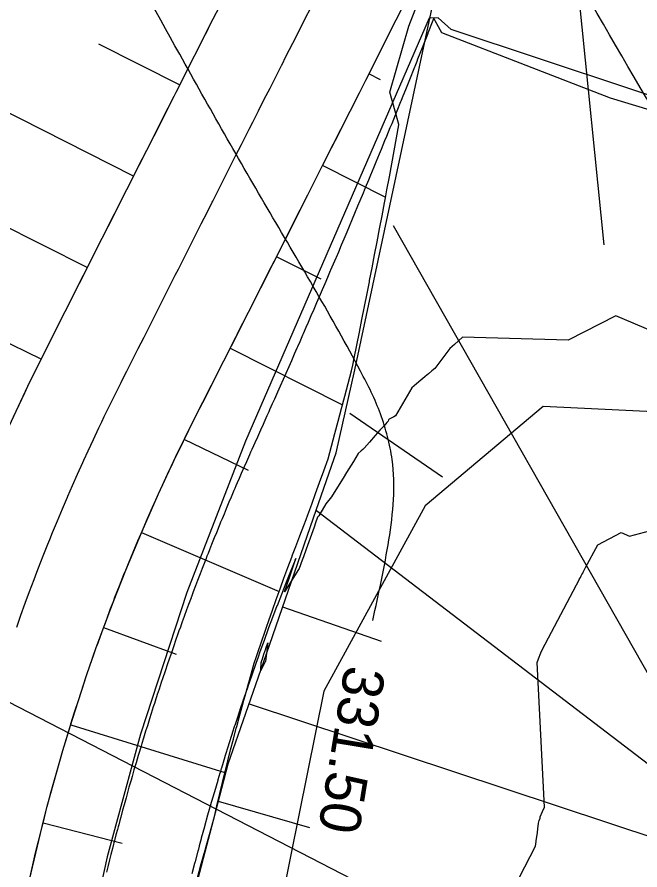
# Model space of a CAD drawing. Extents: x -564043 to -563833, y -1163561 to -1163412.
# Drawn here: x -563863.75 to -563856.15, y -1163500.35 to -1163489.94 of the extents above; entities that cross this region are included whole.
import ezdxf

# ---------------------------------------------------------------- set-up
doc = ezdxf.new("R2010")
doc.units = 0
for name, color, linetype in [('5', 7, 'Continuous'), ('Default', 7, 'Continuous'), ('Line', 7, 'Continuous'), ('Vrstva 24', 7, 'Continuous'), ('Vrstva 25', 7, 'Continuous'), ('Vrstva 26', 7, 'Continuous')]:
    doc.layers.add(name, color=color, linetype=linetype)

msp = doc.modelspace()

# ---------------------------------------------------------------- linework, layer by layer
for points in [[(-563863.593, -1163500.434), (-563863.56, -1163500.289), (-563863.526, -1163500.144), (-563863.491, -1163500), (-563863.455, -1163499.856), (-563863.446, -1163499.819), (-563863.419, -1163499.711), (-563863.383, -1163499.573), (-563863.381, -1163499.568), (-563863.343, -1163499.424), (-563863.304, -1163499.281), (-563863.264, -1163499.137), (-563863.223, -1163498.995), (-563863.193, -1163498.893), (-563863.181, -1163498.852), (-563863.138, -1163498.71), (-563863.104, -1163498.599), (-563863.094, -1163498.567), (-563863.05, -1163498.426), (-563863.004, -1163498.284), (-563862.958, -1163498.143), (-563862.911, -1163498.002), (-563862.903, -1163497.978), (-563862.863, -1163497.861), (-563862.814, -1163497.721), (-563862.785, -1163497.638), (-563862.764, -1163497.581), (-563862.714, -1163497.441), (-563862.662, -1163497.301), (-563862.61, -1163497.162), (-563862.576, -1163497.075), (-563862.557, -1163497.023), (-563862.503, -1163496.885), (-563862.448, -1163496.747), (-563862.426, -1163496.692), (-563862.392, -1163496.609), (-563862.335, -1163496.472), (-563862.278, -1163496.334), (-563862.219, -1163496.198), (-563862.214, -1163496.186), (-563862.16, -1163496.061), (-563862.1, -1163495.925), (-563862.039, -1163495.79), (-563862.026, -1163495.761), (-563861.978, -1163495.654), (-563861.915, -1163495.52), (-563861.852, -1163495.385), (-563861.817, -1163495.312), (-563861.787, -1163495.251), (-563861.722, -1163495.117), (-563861.657, -1163494.984), (-563861.59, -1163494.851), (-563861.589, -1163494.849), (-563861.52, -1163494.713), (-563861.45, -1163494.575), (-563861.38, -1163494.436), (-563861.31, -1163494.299), (-563861.24, -1163494.16), (-563861.17, -1163494.022), (-563861.1, -1163493.884), (-563861.031, -1163493.746), (-563860.961, -1163493.608), (-563860.928, -1163493.544), (-563860.891, -1163493.47), (-563860.821, -1163493.331), (-563860.751, -1163493.193), (-563860.681, -1163493.055), (-563860.611, -1163492.917), (-563860.541, -1163492.779), (-563860.477, -1163492.652), (-563860.471, -1163492.64), (-563860.401, -1163492.502), (-563860.331, -1163492.364), (-563860.261, -1163492.226), (-563860.192, -1163492.088), (-563860.122, -1163491.95), (-563860.052, -1163491.811), (-563860.026, -1163491.76), (-563859.982, -1163491.673), (-563859.912, -1163491.535), (-563859.842, -1163491.397), (-563859.772, -1163491.259), (-563859.702, -1163491.121), (-563859.632, -1163490.982), (-563859.63, -1163490.978), (-563859.574, -1163490.867), (-563859.495, -1163490.71), (-563859.123, -1163489.975), (-563858.671, -1163489.083)], [(-563861.556, -1163500.472), (-563861.521, -1163500.34), (-563861.512, -1163500.306), (-563861.485, -1163500.208), (-563861.45, -1163500.081), (-563861.449, -1163500.077), (-563861.412, -1163499.946), (-563861.374, -1163499.815), (-563861.34, -1163499.683), (-563861.309, -1163499.55), (-563861.286, -1163499.455), (-563861.277, -1163499.417), (-563861.245, -1163499.285), (-563861.219, -1163499.182), (-563861.212, -1163499.152), (-563861.179, -1163499.019), (-563861.145, -1163498.887), (-563861.111, -1163498.754), (-563861.076, -1163498.622), (-563861.07, -1163498.599), (-563861.041, -1163498.489), (-563861.005, -1163498.357), (-563860.984, -1163498.279), (-563860.969, -1163498.225), (-563860.932, -1163498.092), (-563860.895, -1163497.96), (-563860.857, -1163497.828), (-563860.83, -1163497.746), (-563860.814, -1163497.698), (-563860.769, -1163497.568), (-563860.725, -1163497.438), (-563860.707, -1163497.386), (-563860.68, -1163497.308), (-563860.634, -1163497.179), (-563860.588, -1163497.049), (-563860.541, -1163496.92), (-563860.537, -1163496.909), (-563860.494, -1163496.791), (-563860.446, -1163496.661), (-563860.398, -1163496.532), (-563860.388, -1163496.505), (-563860.35, -1163496.403), (-563860.301, -1163496.274), (-563860.251, -1163496.146), (-563860.224, -1163496.075), (-563860.201, -1163496.017), (-563860.155, -1163495.886), (-563860.109, -1163495.755), (-563860.062, -1163495.624), (-563860.061, -1163495.622), (-563860.008, -1163495.478), (-563859.954, -1163495.332), (-563859.913, -1163495.179), (-563859.872, -1163495.026), (-563859.831, -1163494.873), (-563859.791, -1163494.72), (-563859.751, -1163494.567), (-563859.71, -1163494.414), (-563859.671, -1163494.26), (-563859.655, -1163494.189), (-563859.637, -1163494.104), (-563859.605, -1163493.946), (-563859.573, -1163493.789), (-563859.542, -1163493.631), (-563859.51, -1163493.474), (-563859.479, -1163493.316), (-563859.451, -1163493.171), (-563859.448, -1163493.158), (-563859.417, -1163493), (-563859.387, -1163492.842), (-563859.356, -1163492.684), (-563859.326, -1163492.526), (-563859.296, -1163492.367), (-563859.266, -1163492.209), (-563859.255, -1163492.149), (-563859.237, -1163492.05), (-563859.207, -1163491.892), (-563859.178, -1163491.733), (-563859.149, -1163491.574), (-563859.12, -1163491.415), (-563859.092, -1163491.256), (-563859.091, -1163491.251), (-563859.136, -1163491.089), (-563859.2, -1163490.859), (-563858.97, -1163490.052), (-563858.608, -1163489.115)], [(-563863.757, -1163497.389), (-563863.727, -1163497.303), (-563863.706, -1163497.243), (-563863.653, -1163497.097), (-563863.599, -1163496.952), (-563863.545, -1163496.807), (-563863.51, -1163496.716), (-563863.489, -1163496.663), (-563863.433, -1163496.518), (-563863.376, -1163496.374), (-563863.353, -1163496.317), (-563863.318, -1163496.231), (-563863.259, -1163496.088), (-563863.199, -1163495.945), (-563863.138, -1163495.802), (-563863.133, -1163495.79), (-563863.076, -1163495.66), (-563863.014, -1163495.519), (-563862.95, -1163495.377), (-563862.937, -1163495.348), (-563862.886, -1163495.237), (-563862.821, -1163495.096), (-563862.755, -1163494.956), (-563862.719, -1163494.88), (-563862.688, -1163494.816), (-563862.62, -1163494.677), (-563862.552, -1163494.538), (-563862.482, -1163494.4), (-563862.481, -1163494.397), (-563862.412, -1163494.262), (-563862.342, -1163494.123), (-563862.272, -1163493.985), (-563862.202, -1163493.847), (-563862.133, -1163493.709), (-563862.063, -1163493.571), (-563861.993, -1163493.433), (-563861.923, -1163493.294), (-563861.853, -1163493.156), (-563861.821, -1163493.093), (-563861.783, -1163493.018), (-563861.713, -1163492.88), (-563861.643, -1163492.742), (-563861.573, -1163492.604), (-563861.503, -1163492.465), (-563861.433, -1163492.327), (-563861.369, -1163492.2), (-563861.364, -1163492.189), (-563861.294, -1163492.051), (-563861.224, -1163491.913), (-563861.154, -1163491.774), (-563861.084, -1163491.636), (-563861.014, -1163491.498), (-563860.944, -1163491.36), (-563860.918, -1163491.308), (-563860.874, -1163491.222), (-563860.804, -1163491.084), (-563860.734, -1163490.945), (-563860.664, -1163490.807), (-563860.594, -1163490.669), (-563860.525, -1163490.531), (-563860.522, -1163490.527), (-563860.466, -1163490.416), (-563860.387, -1163490.259), (-563860.015, -1163489.524)], [(-563865.785, -1163501.206), (-563865.619, -1163500.343), (-563865.574, -1163500.129), (-563865.385, -1163499.33), (-563865.317, -1163499.063), (-563865.111, -1163498.327), (-563865.015, -1163498.009), (-563864.797, -1163497.335), (-563864.669, -1163496.968), (-563864.528, -1163496.58), (-563864.443, -1163496.357), (-563864.28, -1163495.943), (-563864.051, -1163495.394), (-563863.848, -1163494.935), (-563863.62, -1163494.448), (-563863.373, -1163493.946), (-563863.165, -1163493.533), (-563862.713, -1163492.641), (-563862.262, -1163491.749), (-563861.987, -1163491.206), (-563861.81, -1163490.857), (-563861.359, -1163489.964), (-563861.279, -1163489.807)], [(-563863.795, -1163494.819), (-563863.727, -1163494.673), (-563863.658, -1163494.527), (-563863.62, -1163494.448), (-563863.589, -1163494.382), (-563863.518, -1163494.237), (-563863.447, -1163494.092), (-563863.374, -1163493.948), (-563863.373, -1163493.946), (-563863.305, -1163493.81), (-563863.235, -1163493.672), (-563863.165, -1163493.533), (-563863.095, -1163493.396), (-563863.025, -1163493.257), (-563862.955, -1163493.119), (-563862.885, -1163492.981), (-563862.815, -1163492.843), (-563862.745, -1163492.705), (-563862.713, -1163492.641), (-563862.675, -1163492.567), (-563862.605, -1163492.428), (-563862.535, -1163492.29), (-563862.466, -1163492.152), (-563862.396, -1163492.014), (-563862.326, -1163491.876), (-563862.262, -1163491.749), (-563862.256, -1163491.738), (-563862.186, -1163491.599), (-563862.116, -1163491.461), (-563862.046, -1163491.323), (-563861.976, -1163491.185), (-563861.906, -1163491.047), (-563861.836, -1163490.908), (-563861.81, -1163490.857), (-563861.766, -1163490.77), (-563861.696, -1163490.632), (-563861.627, -1163490.494), (-563861.557, -1163490.356), (-563861.487, -1163490.218), (-563861.417, -1163490.079), (-563861.415, -1163490.075), (-563861.359, -1163489.964), (-563861.279, -1163489.807)], [(-563863.62, -1163500.557), (-563863.446, -1163499.819), (-563863.383, -1163499.573), (-563863.193, -1163498.893), (-563863.104, -1163498.599), (-563862.903, -1163497.978), (-563862.785, -1163497.638), (-563862.654, -1163497.28), (-563862.576, -1163497.075), (-563862.426, -1163496.692), (-563862.214, -1163496.186), (-563862.026, -1163495.761), (-563861.817, -1163495.312), (-563861.589, -1163494.849), (-563861.38, -1163494.436), (-563860.928, -1163493.544), (-563860.477, -1163492.652), (-563860.202, -1163492.109), (-563860.026, -1163491.76), (-563859.574, -1163490.867), (-563859.495, -1163490.71)], [(-563855.435, -1163494.017), (-563856.443, -1163493.586), (-563857.024, -1163493.885), (-563858.314, -1163493.847), (-563858.363, -1163493.892), (-563858.414, -1163493.938), (-563858.468, -1163493.988), (-563858.651, -1163494.229), (-563858.689, -1163494.261), (-563858.73, -1163494.296), (-563858.769, -1163494.329), (-563858.774, -1163494.333), (-563858.822, -1163494.374), (-563858.875, -1163494.418), (-563858.933, -1163494.467), (-563859.131, -1163494.809), (-563859.152, -1163494.82), (-563859.176, -1163494.834), (-563859.201, -1163494.847), (-563859.208, -1163494.851), (-563859.22, -1163494.858), (-563859.223, -1163494.872), (-563859.239, -1163494.89), (-563859.277, -1163494.933), (-563859.323, -1163494.985), (-563859.38, -1163495.049), (-563859.452, -1163495.13), (-563859.516, -1163495.202), (-563859.532, -1163495.22), (-563859.55, -1163495.236), (-563859.588, -1163495.27), (-563859.647, -1163495.365), (-563859.731, -1163495.502), (-563859.772, -1163495.568), (-563859.819, -1163495.646), (-563859.914, -1163495.799), (-563859.984, -1163495.881), (-563860.055, -1163496.01), (-563860.068, -1163496.027), (-563860.083, -1163496.044), (-563860.108, -1163496.116), (-563860.127, -1163496.166), (-563860.175, -1163496.301), (-563860.224, -1163496.436), (-563860.257, -1163496.528), (-563860.272, -1163496.571), (-563860.308, -1163496.67), (-563860.318, -1163496.685), (-563860.486, -1163496.955), (-563860.463, -1163496.887), (-563860.451, -1163496.852), (-563860.436, -1163496.807), (-563860.403, -1163496.707), (-563860.359, -1163496.574), (-563860.358, -1163496.571), (-563860.351, -1163496.551), (-563860.359, -1163496.571), (-563860.359, -1163496.571), (-563860.416, -1163496.71), (-563860.416, -1163496.71), (-563860.471, -1163496.849), (-563860.471, -1163496.849), (-563860.5, -1163496.924), (-563860.501, -1163496.925), (-563860.525, -1163496.989), (-563860.526, -1163496.989), (-563860.579, -1163497.128), (-563860.58, -1163497.129), (-563860.633, -1163497.268), (-563860.633, -1163497.269), (-563860.681, -1163497.397), (-563860.681, -1163497.397), (-563860.685, -1163497.409), (-563860.685, -1163497.409), (-563860.737, -1163497.549), (-563860.737, -1163497.55), (-563860.788, -1163497.69), (-563860.788, -1163497.69), (-563860.811, -1163497.753), (-563860.811, -1163497.754), (-563860.838, -1163497.831), (-563860.838, -1163497.832), (-563860.888, -1163497.972), (-563860.888, -1163497.973), (-563860.936, -1163498.113), (-563860.937, -1163498.115), (-563860.985, -1163498.255), (-563860.985, -1163498.255), (-563860.992, -1163498.276), (-563860.993, -1163498.279), (-563861.032, -1163498.397), (-563861.033, -1163498.4), (-563861.079, -1163498.539), (-563861.079, -1163498.54), (-563861.095, -1163498.59), (-563861.096, -1163498.593), (-563861.125, -1163498.681), (-563861.126, -1163498.685), (-563861.17, -1163498.824), (-563861.171, -1163498.828), (-563861.214, -1163498.966), (-563861.216, -1163498.971), (-563861.258, -1163499.109), (-563861.259, -1163499.111), (-563861.275, -1163499.164), (-563861.276, -1163499.168), (-563861.301, -1163499.252), (-563861.303, -1163499.258), (-563861.343, -1163499.396), (-563861.344, -1163499.397), (-563861.355, -1163499.435), (-563861.356, -1163499.439), (-563861.385, -1163499.539), (-563861.387, -1163499.546), (-563861.426, -1163499.683), (-563861.464, -1163499.82), (-563861.466, -1163499.827), (-563861.504, -1163499.964), (-563861.505, -1163499.971), (-563861.528, -1163500.056), (-563861.529, -1163500.061), (-563861.543, -1163500.113), (-563861.544, -1163500.116), (-563861.58, -1163500.254), (-563861.582, -1163500.26), (-563861.589, -1163500.286), (-563861.589, -1163500.287), (-563861.618, -1163500.4)], [(-563851.082, -1163505.728), (-563849.948, -1163501.531), (-563849.628, -1163500.347), (-563850.165, -1163499.681), (-563852.128, -1163495.731), (-563853.44, -1163495.48), (-563855.061, -1163494.806), (-563857.328, -1163494.696), (-563858.771, -1163495.906), (-563860.007, -1163498.17), (-563860.512, -1163500.673), (-563860.896, -1163502.23)], [(-563859.058, -1163503.231), (-563857.424, -1163500.06), (-563857.416, -1163500.003), (-563857.414, -1163499.991), (-563857.404, -1163499.921), (-563857.401, -1163499.894), (-563857.395, -1163499.851), (-563857.385, -1163499.781), (-563857.38, -1163499.748), (-563857.366, -1163499.72), (-563857.367, -1163499.709), (-563857.367, -1163499.705), (-563857.337, -1163499.637), (-563857.314, -1163499.585), (-563857.403, -1163497.819), (-563857.398, -1163497.805), (-563857.377, -1163497.753), (-563857.365, -1163497.722), (-563857.357, -1163497.702), (-563857.342, -1163497.665), (-563856.887, -1163496.804), (-563856.887, -1163496.803), (-563856.885, -1163496.799), (-563856.875, -1163496.781), (-563856.866, -1163496.763), (-563856.86, -1163496.752), (-563856.856, -1163496.745), (-563856.847, -1163496.728), (-563856.842, -1163496.718), (-563856.812, -1163496.661), (-563856.664, -1163496.381), (-563856.379, -1163496.234), (-563856.277, -1163496.278), (-563855.24, -1163496)]]:
    msp.add_lwpolyline(points)
for points in [[(-563864.657, -1163510.241), (-563863.634, -1163509.902), (-563862.371, -1163510.364), (-563856.258, -1163509.872), (-563849.971, -1163509.495), (-563846.657, -1163503.058), (-563846.814, -1163502.626), (-563847.162, -1163502.341), (-563848.492, -1163499.244), (-563850.901, -1163494.112), (-563854.114, -1163491.532), (-563858.451, -1163490.091), (-563858.61, -1163489.95), (-563858.72, -1163489.955), (-563860.965, -1163495.118), (-563861.68, -1163496.963), (-563862.247, -1163498.693), (-563862.652, -1163500.191), (-563862.88, -1163501.229), (-563863.177, -1163502.77), (-563863.416, -1163504.013), (-563864.472, -1163509.23)], [(-563860.775, -1163497.874), (-563860.774, -1163497.856), (-563860.772, -1163497.824), (-563860.764, -1163497.796), (-563860.757, -1163497.773), (-563860.738, -1163497.717), (-563860.717, -1163497.654), (-563860.715, -1163497.648), (-563860.693, -1163497.58), (-563860.72, -1163497.806), (-563860.723, -1163497.812), (-563860.778, -1163497.915)]]:
    msp.add_lwpolyline(points, close=True)
at = {"layer": '5'}
msp.add_line((-563871.424, -1163494.398), (-563841.172, -1163509.993), dxfattribs=at)
at = {"layer": 'Default'}
for points in [[(-563861.871, -1163501.708), (-563861.355, -1163499.743), (-563861.175, -1163499.057), (-563860.744, -1163497.818), (-563860.132, -1163496.055), (-563859.88, -1163495.331), (-563859.856, -1163495.261), (-563859.628, -1163494.247), (-563858.554, -1163489.211), (-563856.89, -1163488.106), (-563853.44, -1163488.662), (-563853.44, -1163488.662), (-563852.435, -1163488.408), (-563849.66, -1163490.902), (-563849.248, -1163491.704), (-563847.479, -1163495.149), (-563847.069, -1163497.206), (-563847.056, -1163497.268), (-563846.963, -1163497.738), (-563846.685, -1163499.13), (-563846.607, -1163499.521), (-563845.777, -1163503.681)], [(-563854.17, -1163491.64), (-563856.508, -1163490.933), (-563858.568, -1163490.135), (-563858.628, -1163490.024), (-563858.633, -1163490.015), (-563858.647, -1163489.988), (-563858.652, -1163489.979), (-563858.665, -1163489.956), (-563858.675, -1163489.981), (-563858.675, -1163489.983), (-563858.737, -1163490.139), (-563858.738, -1163490.141), (-563858.747, -1163490.165), (-563858.752, -1163490.176), (-563858.8, -1163490.297), (-563858.808, -1163490.317), (-563858.862, -1163490.455), (-563858.873, -1163490.482), (-563858.925, -1163490.613), (-563858.938, -1163490.646), (-563858.988, -1163490.77), (-563859.004, -1163490.808), (-563859.052, -1163490.928), (-563859.069, -1163490.97), (-563859.07, -1163490.974), (-563859.117, -1163491.089), (-563859.134, -1163491.132), (-563859.138, -1163491.14), (-563859.179, -1163491.243), (-563859.2, -1163491.293), (-563859.243, -1163491.4), (-563859.265, -1163491.453), (-563859.308, -1163491.557), (-563859.331, -1163491.613), (-563859.372, -1163491.714), (-563859.397, -1163491.773), (-563859.437, -1163491.871), (-563859.462, -1163491.932), (-563859.463, -1163491.932), (-563859.502, -1163492.027), (-563859.529, -1163492.091), (-563859.567, -1163492.184), (-563859.595, -1163492.25), (-563859.633, -1163492.34), (-563859.661, -1163492.408), (-563859.698, -1163492.497), (-563859.728, -1163492.567), (-563859.764, -1163492.653), (-563859.795, -1163492.725), (-563859.83, -1163492.809), (-563859.858, -1163492.875), (-563859.862, -1163492.882), (-563859.893, -1163492.957), (-563859.925, -1163493.031), (-563859.929, -1163493.04), (-563859.963, -1163493.121), (-563859.996, -1163493.197), (-563860.028, -1163493.272), (-563860.063, -1163493.354), (-563860.096, -1163493.43), (-563860.131, -1163493.511), (-563860.165, -1163493.588), (-563860.199, -1163493.668), (-563860.227, -1163493.731), (-563860.26, -1163493.809), (-563860.267, -1163493.824), (-563860.302, -1163493.904), (-563860.329, -1163493.966), (-563860.336, -1163493.981), (-563860.368, -1163494.054), (-563860.404, -1163494.136), (-563860.436, -1163494.209), (-563860.473, -1163494.292), (-563860.504, -1163494.364), (-563860.541, -1163494.448), (-563860.573, -1163494.519), (-563860.61, -1163494.603), (-563860.637, -1163494.663), (-563860.669, -1163494.735), (-563860.68, -1163494.758), (-563860.702, -1163494.809), (-563860.74, -1163494.894), (-563860.749, -1163494.914), (-563860.78, -1163494.983), (-563860.819, -1163495.068), (-563860.85, -1163495.137), (-563860.867, -1163495.176), (-563860.887, -1163495.221), (-563860.901, -1163495.252), (-563860.916, -1163495.286), (-563860.953, -1163495.368), (-563860.98, -1163495.429), (-563861.016, -1163495.512), (-563861.043, -1163495.574), (-563861.065, -1163495.625), (-563861.082, -1163495.664), (-563861.095, -1163495.695), (-563861.105, -1163495.718), (-563861.14, -1163495.8), (-563861.166, -1163495.862), (-563861.2, -1163495.945), (-563861.226, -1163496.007), (-563861.249, -1163496.064), (-563861.267, -1163496.106), (-563861.278, -1163496.132), (-563861.286, -1163496.152), (-563861.319, -1163496.235), (-563861.345, -1163496.298), (-563861.378, -1163496.38), (-563861.403, -1163496.443), (-563861.42, -1163496.488), (-563861.434, -1163496.522), (-563861.449, -1163496.56), (-563861.46, -1163496.589), (-563861.492, -1163496.672), (-563861.517, -1163496.735), (-563861.548, -1163496.818), (-563861.573, -1163496.882), (-563861.601, -1163496.957), (-563861.623, -1163497.016), (-563861.626, -1163497.023), (-563861.628, -1163497.028), (-563861.658, -1163497.111), (-563861.682, -1163497.175), (-563861.712, -1163497.258), (-563861.736, -1163497.322), (-563861.749, -1163497.36), (-563861.759, -1163497.389), (-563861.776, -1163497.434), (-563861.788, -1163497.47), (-563861.817, -1163497.552), (-563861.84, -1163497.617), (-563861.869, -1163497.7), (-563861.891, -1163497.765), (-563861.92, -1163497.848), (-563861.942, -1163497.913), (-563861.946, -1163497.926), (-563861.949, -1163497.936), (-563861.973, -1163498.006), (-563861.992, -1163498.062), (-563862.019, -1163498.145), (-563862.041, -1163498.21), (-563862.05, -1163498.24), (-563862.058, -1163498.264), (-563862.075, -1163498.318), (-563862.089, -1163498.359), (-563862.115, -1163498.443), (-563862.136, -1163498.508), (-563862.162, -1163498.592), (-563862.183, -1163498.657), (-563862.209, -1163498.742), (-563862.228, -1163498.807), (-563862.238, -1163498.839), (-563862.246, -1163498.864), (-563862.262, -1163498.917), (-563862.274, -1163498.956), (-563862.299, -1163499.042), (-563862.318, -1163499.106), (-563862.325, -1163499.13), (-563862.33, -1163499.147), (-563862.348, -1163499.21), (-563862.361, -1163499.256), (-563862.386, -1163499.342), (-563862.404, -1163499.407), (-563862.422, -1163499.471), (-563862.446, -1163499.557), (-563862.464, -1163499.622), (-563862.487, -1163499.708), (-563862.498, -1163499.748), (-563862.512, -1163499.802), (-563862.519, -1163499.826), (-563862.528, -1163499.859), (-563862.545, -1163499.924), (-563862.567, -1163500.01), (-563862.57, -1163500.022), (-563862.574, -1163500.038), (-563862.588, -1163500.091), (-563862.606, -1163500.162), (-563862.623, -1163500.227), (-563862.644, -1163500.313), (-563862.66, -1163500.379)]]:
    msp.add_lwpolyline(points, dxfattribs=at)
at = {"layer": 'Line'}
for p, q in [((-563856.587, -1163492.721), (-563857.038, -1163488.204)), ((-563862.758, -1163490.266), (-563861.765, -1163490.768)), ((-563862.33, -1163491.884), (-563865.054, -1163490.506)), ((-563859.317, -1163490.707), (-563859.457, -1163490.636)), ((-563860.021, -1163491.751), (-563859.253, -1163492.14)), ((-563863.457, -1163494.115), (-563867.593, -1163492.106)), ((-563864.611, -1163492.132), (-563862.894, -1163492.999)), ((-563854.949, -1163499.897), (-563859.159, -1163492.49)), ((-563860.042, -1163493.141), (-563860.586, -1163492.867)), ((-563861.15, -1163493.982), (-563859.778, -1163494.673)), ((-563858.558, -1163495.555), (-563859.689, -1163494.781)), ((-563860.927, -1163495.476), (-563861.711, -1163495.099)), ((-563860.099, -1163495.962), (-563854.949, -1163499.897)), ((-563862.233, -1163496.234), (-563860.554, -1163496.954)), ((-563859.304, -1163497.561), (-563860.509, -1163497.143)), ((-563861.808, -1163497.722), (-563862.695, -1163497.396)), ((-563860.92, -1163498.323), (-563855.149, -1163500.234)), ((-563863.096, -1163498.579), (-563861.215, -1163499.163)), ((-563860.18, -1163499.837), (-563861.295, -1163499.515)), ((-563862.469, -1163500.028), (-563863.435, -1163499.782))]:
    msp.add_line(p, q, dxfattribs=at)
at = {"layer": 'Vrstva 24'}
for points in [[(-563834.56, -1163494.639), (-563836.366, -1163491.682), (-563837.263, -1163490.402), (-563838.091, -1163489.323), (-563838.932, -1163488.255), (-563840.679, -1163486.176), (-563843.599, -1163482.931), (-563845.377, -1163480.993), (-563847.69, -1163478.523), (-563848.871, -1163477.312), (-563850.082, -1163476.13), (-563853.183, -1163473.259), (-563856.324, -1163470.434), (-563856.74, -1163470.064), (-563856.896, -1163469.927), (-563857.179, -1163469.672), (-563858.782, -1163468.194), (-563860.374, -1163466.704), (-563861.969, -1163465.217), (-563862.806, -1163464.448)], [(-563852.947, -1163500.287), (-563852.983, -1163499.934), (-563853.278, -1163497.907), (-563853.324, -1163497.501), (-563853.384, -1163496.604), (-563853.408, -1163496.155), (-563853.449, -1163495.707), (-563853.76, -1163494.797), (-563854.364, -1163493.737), (-563856.816, -1163489.636), (-563859.313, -1163485.439), (-563859.915, -1163484.694), (-563860.397, -1163484.207), (-563862.509, -1163482.09), (-563867.011, -1163477.664), (-563868.116, -1163476.702), (-563871.116, -1163474.41), (-563872.986, -1163473.06), (-563873.689, -1163472.566), (-563878.103, -1163469.411), (-563878.316, -1163469.26)], [(-563840.258, -1163509.873), (-563839.896, -1163508.143), (-563839.904, -1163507.091), (-563840.452, -1163504.683), (-563840.841, -1163503.06), (-563841.044, -1163502.221), (-563841.512, -1163500.521), (-563841.78, -1163499.679), (-563842.064, -1163498.842), (-563842.395, -1163498.068), (-563843.845, -1163495.39), (-563845.853, -1163491.78), (-563846.807, -1163490.032), (-563847.876, -1163488.404), (-563852.123, -1163483.19), (-563853.868, -1163481.341), (-563857.18, -1163478.245), (-563858.504, -1163477.011), (-563860.386, -1163475.26)]]:
    msp.add_spline(points, degree=3, dxfattribs=at)
at = {"layer": 'Vrstva 26'}
for points in [[(-563838.029, -1163497.163), (-563838.58, -1163496.19), (-563840.28, -1163493.165), (-563841.199, -1163491.578), (-563841.674, -1163490.793), (-563842.159, -1163490.013), (-563843.649, -1163487.993), (-563844.702, -1163486.757), (-563850.461, -1163480.038), (-563851.089, -1163479.371), (-563851.956, -1163478.574), (-563857.613, -1163473.501), (-563859.731, -1163471.636), (-563864.022, -1163468.083), (-563864.562, -1163467.631), (-563865.045, -1163467.216), (-563865.679, -1163466.68)], [(-563859.41, -1163497.306), (-563859.213, -1163496.32), (-563859.173, -1163495.343), (-563859.23, -1163495.062), (-563859.315, -1163494.786), (-563859.559, -1163494.264), (-563860.664, -1163492.33), (-563861.767, -1163490.395), (-563863.612, -1163487.077), (-563864.619, -1163485.435), (-563865.167, -1163484.642), (-563865.744, -1163483.864), (-563868.01, -1163481.46), (-563871.348, -1163478.665), (-563874.529, -1163476.131), (-563879.25, -1163472.365), (-563881.038, -1163471.025), (-563881.839, -1163470.479), (-563883.542, -1163469.415), (-563886.341, -1163467.718)], [(-563846.143, -1163505.119), (-563846.16, -1163504.298), (-563846.784, -1163499.435), (-563846.859, -1163499.141), (-563847.15, -1163498.47), (-563847.685, -1163497.291), (-563847.809, -1163497.032), (-563850.257, -1163492.396), (-563853.06, -1163487.093), (-563853.131, -1163486.997), (-563856.933, -1163483.04), (-563859.434, -1163480.56), (-563863.484, -1163476.533), (-563865.168, -1163474.917), (-563866.123, -1163474.143), (-563868.988, -1163472.112)]]:
    msp.add_spline(points, degree=3, dxfattribs=at)

# ---------------------------------------------------------------- texts
at = {"layer": 'Vrstva 25'}
msp.add_text('331.50', height=0.5, rotation=260.6689, dxfattribs=at).set_placement((-563859.746, -1163497.839))

doc.saveas('drawing.dxf')
